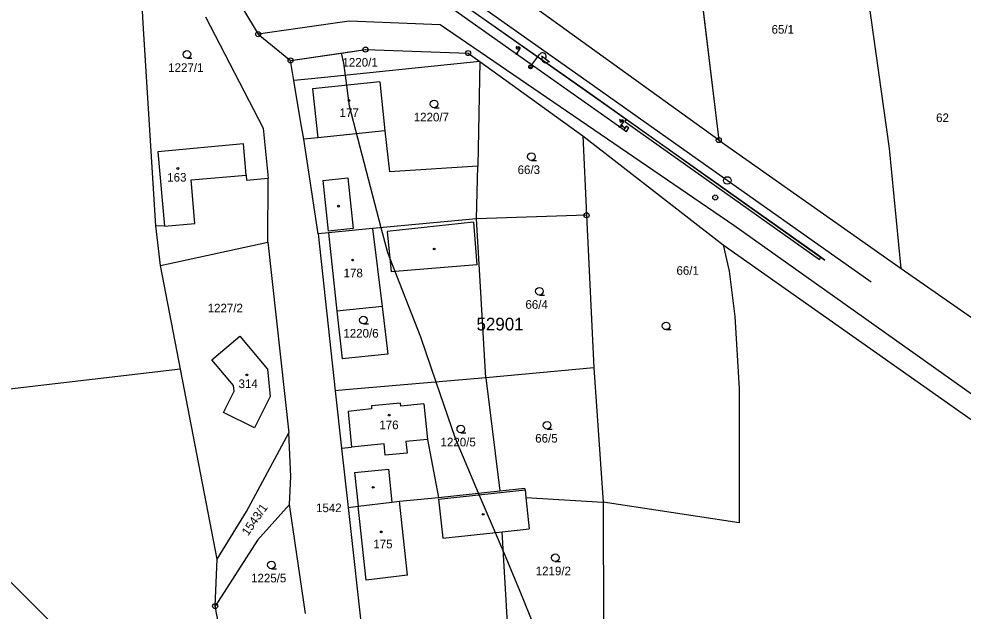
# Model space of a CAD drawing. Extents: x -777175 to -776673, y -1110537 to -1110036.
# Drawn here: x -776987.6 to -776801.4, y -1110431.1 to -1110314.3 of the extents above; entities that cross this region are included whole.
import ezdxf

# ---------------------------------------------------------------- set-up
doc = ezdxf.new("R2010")
doc.units = 0
for name, color, linetype in [('BPEJ', 7, 'Continuous'), ('GD_Demolice', 7, 'Continuous'), ('GD_Nový stav', 7, 'Continuous'), ('GD_Starý stav', 7, 'Continuous'), ('Katastr_HRANICE DRÁHY', 7, 'Continuous'), ('Katastr_Hranice parcel', 7, 'Continuous'), ('Katastr_Parcelní čísla', 7, 'Continuous'), ('Katastr_Slučkované čáry', 7, 'Continuous'), ('Katastr_Značky kultur', 7, 'Continuous'), ('Vrstva 7', 7, 'Continuous')]:
    doc.layers.add(name, color=color, linetype=linetype)

msp = doc.modelspace()

# ---------------------------------------------------------------- linework, layer by layer
at = {"layer": 'BPEJ'}
for points in [[(-776942.64, -1110471.49), (-776943.89, -1110463.76), (-776944.49, -1110457.52), (-776946.46, -1110445.63), (-776946.62, -1110444.42), (-776947.54, -1110437.37), (-776947.6, -1110436.89), (-776948.9, -1110430.12), (-776948.48, -1110420.89), (-776959.71, -1110362.93), (-776960.61, -1110355.15), (-776963.07, -1110315.22), (-776964.17, -1110295.07), (-776960.44, -1110293.63), (-776956.24, -1110294.15), (-776954.44, -1110298.36), (-776953.88, -1110294.2), (-776949.89, -1110285), (-776940.9, -1110291.45)], [(-776940.9, -1110291.45), (-776945.85, -1110300.04), (-776946.2, -1110307.65), (-776940.41, -1110317.34), (-776934.03, -1110322.5), (-776924.02, -1110321.07)], [(-776924.02, -1110321.07), (-776919.29, -1110320.39), (-776899.05, -1110321.06), (-776896.7, -1110322.75), (-776876.4, -1110337.37), (-776875.66, -1110353.06), (-776874.23, -1110383.12), (-776872.38, -1110409.66), (-776872.36, -1110434.4)], [(-776871.27, -1110465.42), (-776878.74, -1110452.04), (-776879.88, -1110449.23), (-776883.66, -1110439.87), (-776885.8, -1110434.57), (-776888.9, -1110426.9), (-776892.08, -1110419.38), (-776896.95, -1110407.86), (-776901.52, -1110397.06), (-776905.33, -1110385.94), (-776908.38, -1110377.06), (-776914.87, -1110360.44), (-776916.16, -1110355.5), (-776922.42, -1110331.54), (-776922.97, -1110327.43), (-776923.23, -1110325.46), (-776923.55, -1110323.06), (-776924.02, -1110321.07)]]:
    msp.add_lwpolyline(points, dxfattribs=at)
at = {"layer": 'Defpoints'}
msp.add_line((-776876.14, -1110537.25), (-777174.79, -1110241.95), dxfattribs=at)
at = {"layer": 'GD_Demolice'}
for p, q in [((-776886.5, -1110323.47), (-776884.98, -1110321.33)), ((-776884.55, -1110321.64), (-776882.96, -1110322.76)), ((-776887.07, -1110323.67), (-776886.42, -1110323.55)), ((-776887.05, -1110323.94), (-776886.34, -1110323.82))]:
    msp.add_line(p, q, dxfattribs=at)
msp.add_lwpolyline([(-776868.13, -1110334.57), (-776829.78, -1110361.74), (-776829.49, -1110361.33), (-776867.84, -1110334.16)], close=True, dxfattribs=at)
msp.add_circle((-776886.71, -1110323.78), 0.375, dxfattribs=at)
msp.add_circle((-776886.71, -1110323.78), 0.375, dxfattribs=at)
for centre, start, end in [((-776884.37, -1110321.76), 324.7342, 144.7342), ((-776883.76, -1110322.21), 144.0316, 325.4368)]:
    msp.add_arc(centre, 0.75, start, end, dxfattribs=at)
at = {"layer": 'GD_Nový stav'}
for p, q in [((-776909.86, -1110306.76), (-776889.46, -1110321.21)), ((-776888.97, -1110320.18), (-776889.57, -1110319.75)), ((-776889.38, -1110321.09), (-776888.81, -1110320.29)), ((-776889.48, -1110321.35), (-776889.52, -1110321.08)), ((-776889.46, -1110321.21), (-776868.26, -1110336.2)), ((-776889.38, -1110321.32), (-776889.42, -1110321.08)), ((-776868.58, -1110334.6), (-776869.18, -1110334.17)), ((-776868.99, -1110335.51), (-776868.42, -1110334.71)), ((-776868.59, -1110335.23), (-776868.81, -1110335.53)), ((-776868.13, -1110334.57), (-776867.84, -1110334.16)), ((-776869.09, -1110335.77), (-776869.13, -1110335.5)), ((-776868.98, -1110335.74), (-776869.02, -1110335.5)), ((-776868.7, -1110335.38), (-776868.09, -1110335.81)), ((-776868.09, -1110335.81), (-776868.34, -1110336.17)), ((-776868.34, -1110336.17), (-776867.83, -1110336.53)), ((-776867.84, -1110335.46), (-776868.09, -1110335.81)), ((-776867.33, -1110335.82), (-776867.84, -1110335.46)), ((-776867.83, -1110336.53), (-776867.33, -1110335.82))]:
    msp.add_line(p, q, dxfattribs=at)
for centre in [(-776889.46, -1110321.21), (-776889.46, -1110321.21), (-776869.07, -1110335.63), (-776869.07, -1110335.63)]:
    msp.add_circle(centre, 0.141, dxfattribs=at)
for centre, start, end in [((-776889.27, -1110319.97), 143.98, 325.3852), ((-776889.04, -1110320.13), 324.6826, 144.6826), ((-776868.88, -1110334.39), 143.98, 325.3852), ((-776868.65, -1110334.55), 324.6826, 144.6826)]:
    msp.add_arc(centre, 0.281, start, end, dxfattribs=at)
at = {"layer": 'GD_Starý stav'}
for points in [[(-776933.32, -1110287.93), (-776932.41, -1110288.39), (-776916.53, -1110299.75), (-776903.36, -1110309.07), (-776875.06, -1110329), (-776849.25, -1110347.3), (-776828.68, -1110361.9)], [(-776828.68, -1110361.9), (-776829.18, -1110361.55), (-776849.26, -1110347.33), (-776875, -1110329.07), (-776903.43, -1110309.03), (-776920.48, -1110296.98), (-776932.53, -1110288.41), (-776933.32, -1110287.93)], [(-776819.55, -1110366.24), (-776848.4, -1110345.85), (-776874.05, -1110327.7), (-776902.43, -1110307.63), (-776922.25, -1110293.6), (-776926.74, -1110290.42), (-776929.88, -1110288.2)]]:
    msp.add_lwpolyline(points, dxfattribs=at)
at = {"layer": 'Katastr_HRANICE DRÁHY'}
for points in [[(-776849.62, -1110338.22), (-776894.76, -1110305.65)], [(-776946.2, -1110307.65), (-776940.41, -1110317.34)], [(-776757.91, -1110417.68), (-776792.98, -1110393.16), (-776846.61, -1110355.09), (-776904.52, -1110315.47), (-776922.51, -1110314.75), (-776940.41, -1110317.34)], [(-776849.62, -1110338.22), (-776813.64, -1110363.55), (-776795.25, -1110376.34), (-776788.84, -1110380.33), (-776748.99, -1110408.66)]]:
    msp.add_lwpolyline(points, dxfattribs=at)
at = {"layer": 'Katastr_Hranice parcel'}
msp.add_line((-776854.31, -1110299.08), (-776849.62, -1110338.22), dxfattribs=at)
for points in [[(-776780.63, -1110277.66), (-776801.34, -1110279.1), (-776814.49, -1110280.25), (-776823.89, -1110281.93), (-776826.29, -1110267.5), (-776831.4, -1110267.85), (-776830.95, -1110273.53), (-776856.55, -1110275.29), (-776856.32, -1110281.19), (-776854.31, -1110299.08), (-776849.62, -1110338.22), (-776894.76, -1110305.65), (-776896.59, -1110304.32), (-776903.91, -1110299.01), (-776906.52, -1110296.78), (-776914.36, -1110290.06), (-776923.15, -1110282.87), (-776931.82, -1110275.9)], [(-776813.64, -1110363.55), (-776815.92, -1110339.86), (-776822.21, -1110295.34), (-776823.89, -1110281.93)], [(-776963.07, -1110315.22), (-776964.17, -1110295.07)], [(-776950.83, -1110313.89), (-776939.43, -1110335.86)], [(-776960.61, -1110355.15), (-776963.07, -1110315.22)], [(-776940.41, -1110317.34), (-776934.03, -1110322.5)], [(-776934.03, -1110322.5), (-776919.29, -1110320.39)], [(-776919.29, -1110320.39), (-776899.05, -1110321.06)], [(-776899.05, -1110321.06), (-776896.7, -1110322.75)], [(-776933.39, -1110326.49), (-776934.03, -1110322.5)], [(-776896.7, -1110322.75), (-776929.92, -1110326.14)], [(-776896.7, -1110322.75), (-776897.12, -1110343.35)], [(-776896.7, -1110322.75), (-776876.4, -1110337.37)], [(-776929.92, -1110326.14), (-776933.39, -1110326.49)], [(-776931.99, -1110334.85), (-776933.39, -1110326.49)], [(-776916.46, -1110326.75), (-776929.7, -1110328.14)], [(-776916.46, -1110326.75), (-776915.42, -1110336.37)], [(-776929.7, -1110328.14), (-776928.66, -1110337.76)], [(-776931.45, -1110338.05), (-776931.99, -1110334.85)], [(-776939.43, -1110335.86), (-776938.47, -1110345.76)], [(-776915.42, -1110336.37), (-776914.54, -1110344.5)], [(-776943.34, -1110338.96), (-776960.2, -1110340.54)], [(-776942.8, -1110345.12), (-776943.34, -1110338.96)], [(-776928.66, -1110337.76), (-776931.45, -1110338.05)], [(-776928.57, -1110356.7), (-776931.45, -1110338.05)], [(-776876.4, -1110337.37), (-776875.66, -1110353.06)], [(-776876.4, -1110337.37), (-776848.72, -1110358.87), (-776847.56, -1110364.06), (-776846.44, -1110372.99), (-776845.59, -1110387.18), (-776845.59, -1110413.73), (-776872.38, -1110409.66)], [(-776960.2, -1110340.54), (-776958.86, -1110355.2)], [(-776897.12, -1110343.35), (-776914.54, -1110344.5)], [(-776897.39, -1110353.76), (-776897.12, -1110343.35)], [(-776942.8, -1110345.12), (-776942.71, -1110346.13)], [(-776942.71, -1110346.13), (-776938.47, -1110345.76)], [(-776938.51, -1110358.35), (-776938.47, -1110345.76)], [(-776897.39, -1110353.76), (-776917.87, -1110355.66)], [(-776875.66, -1110353.06), (-776897.39, -1110353.76)], [(-776895.52, -1110385.09), (-776897.39, -1110353.76)], [(-776875.66, -1110353.06), (-776874.23, -1110383.12)], [(-776959.71, -1110362.93), (-776960.61, -1110355.15)], [(-776958.86, -1110355.2), (-776960.61, -1110355.15)], [(-776917.87, -1110355.66), (-776926.58, -1110356.51)], [(-776926.58, -1110356.51), (-776928.57, -1110356.7)], [(-776928.57, -1110356.7), (-776925.21, -1110387.65)], [(-776959.71, -1110362.93), (-776938.51, -1110358.35)], [(-776938.51, -1110358.35), (-776934.37, -1110395.94)], [(-776848.72, -1110358.87), (-776760.96, -1110420.76)], [(-776948.48, -1110420.89), (-776959.71, -1110362.93)], [(-776915.99, -1110371.01), (-776924.93, -1110371.95)], [(-776924.93, -1110371.95), (-776923.89, -1110381.39)], [(-776915.99, -1110371.01), (-776914.84, -1110380.44)], [(-776949.58, -1110381.53), (-776944.06, -1110376.89)], [(-776944.06, -1110376.89), (-776938.61, -1110383.37)], [(-776945.3, -1110386.64), (-776949.58, -1110381.53)], [(-776914.84, -1110380.44), (-776923.89, -1110381.39)], [(-777023.74, -1110391.3), (-776955.76, -1110383.34)], [(-776938.61, -1110383.37), (-776938.08, -1110388.81)], [(-776874.23, -1110383.12), (-776895.52, -1110385.09)], [(-776874.23, -1110383.12), (-776872.38, -1110409.66)], [(-776895.52, -1110385.09), (-776923.22, -1110387.48)], [(-776895.52, -1110385.09), (-776892.79, -1110407.42)], [(-776945.17, -1110387.71), (-776945.3, -1110386.64)], [(-776947.29, -1110391.94), (-776945.17, -1110387.71)], [(-776938.08, -1110388.81), (-776941.13, -1110394.94)], [(-776923.22, -1110387.48), (-776925.21, -1110387.65)], [(-776925.21, -1110387.65), (-776923.96, -1110398.98)], [(-776912.36, -1110390.08), (-776918.11, -1110390.66)], [(-776918.11, -1110390.66), (-776918.05, -1110391.25)], [(-776912.3, -1110390.67), (-776912.36, -1110390.08)], [(-776907.75, -1110390.21), (-776912.3, -1110390.67)], [(-776907.75, -1110390.21), (-776907.04, -1110397.24)], [(-776941.13, -1110394.94), (-776947.29, -1110391.94)], [(-776918.05, -1110391.25), (-776922.7, -1110391.72)], [(-776922.7, -1110391.72), (-776922.03, -1110398.78)], [(-776942.73, -1110411.46), (-776934.37, -1110395.94)], [(-776933.98, -1110404.58), (-776934.37, -1110395.94)], [(-776907.04, -1110397.24), (-776904.88, -1110408.71)], [(-776923.96, -1110398.98), (-776922.03, -1110398.78)], [(-776923.96, -1110398.98), (-776922.67, -1110410.67)], [(-776934.24, -1110410.08), (-776933.98, -1110404.58)], [(-776904.88, -1110408.71), (-776892.79, -1110407.42)], [(-776892.79, -1110407.42), (-776887.83, -1110406.89)], [(-776887.8, -1110407.19), (-776887.83, -1110406.89)], [(-776887.8, -1110407.19), (-776887.64, -1110408.68)], [(-776920.73, -1110410.44), (-776914.08, -1110409.64)], [(-776914.08, -1110409.64), (-776912.57, -1110409.46)], [(-776912.57, -1110409.46), (-776904.88, -1110408.71)], [(-776887.64, -1110408.68), (-776872.38, -1110409.66)], [(-776887.64, -1110408.68), (-776886.97, -1110414.92)], [(-776872.38, -1110409.66), (-776872.36, -1110434.4)], [(-776948.48, -1110420.89), (-776942.73, -1110411.46)], [(-776934.24, -1110410.08), (-776940.56, -1110417.1)], [(-776931.08, -1110431.61), (-776934.24, -1110410.08)], [(-776922.67, -1110410.67), (-776920.73, -1110410.44)], [(-776922.67, -1110410.67), (-776919.72, -1110437.38)], [(-776892.31, -1110415.49), (-776886.97, -1110414.92)], [(-776940.56, -1110417.1), (-776948.9, -1110430.12)], [(-776891.17, -1110434.64), (-776892.31, -1110415.49)], [(-776948.9, -1110430.12), (-776948.48, -1110420.89)], [(-776947.6, -1110436.89), (-776948.9, -1110430.12)]]:
    msp.add_lwpolyline(points, dxfattribs=at)
at = {"layer": 'Katastr_Slučkované čáry'}
for points in [[(-776915.42, -1110336.37), (-776928.66, -1110337.76)], [(-776953.66, -1110346.08), (-776942.8, -1110345.12)], [(-776952.88, -1110354.65), (-776953.66, -1110346.08)], [(-776927.7, -1110346.2), (-776922.76, -1110345.68)], [(-776927.7, -1110346.2), (-776926.64, -1110356.16)], [(-776922.76, -1110345.68), (-776921.68, -1110355.68)], [(-776958.86, -1110355.2), (-776952.88, -1110354.65)], [(-776921.68, -1110355.68), (-776926.64, -1110356.16)], [(-776917.87, -1110355.66), (-776915.99, -1110371.01)], [(-776897.95, -1110354.4), (-776914.98, -1110356.23)], [(-776897.95, -1110354.4), (-776897.3, -1110362.8)], [(-776926.58, -1110356.51), (-776924.93, -1110371.95)], [(-776914.98, -1110356.23), (-776914.17, -1110364.23)], [(-776897.3, -1110362.8), (-776914.17, -1110364.23)], [(-776915.6, -1110398.12), (-776922.03, -1110398.78)], [(-776915.36, -1110400.39), (-776915.6, -1110398.12)], [(-776907.04, -1110397.24), (-776911.29, -1110397.68)], [(-776911.29, -1110397.68), (-776911.06, -1110399.95)], [(-776911.06, -1110399.95), (-776915.36, -1110400.39)], [(-776921.41, -1110403.78), (-776914.74, -1110403.1)], [(-776921.41, -1110403.78), (-776920.73, -1110410.44)], [(-776914.74, -1110403.1), (-776914.08, -1110409.64)], [(-776904.85, -1110409.01), (-776887.8, -1110407.19)], [(-776910.98, -1110424.03), (-776912.57, -1110409.46)], [(-776904.85, -1110409.01), (-776904.02, -1110416.74)], [(-776919.14, -1110425.01), (-776920.73, -1110410.44)], [(-776904.02, -1110416.74), (-776892.31, -1110415.49)], [(-776910.98, -1110424.03), (-776919.14, -1110425.01)]]:
    msp.add_lwpolyline(points, dxfattribs=at)
at = {"layer": 'Katastr_Značky kultur'}
for p, q in [((-776940.46, -1110317.34), (-776940.36, -1110317.34)), ((-776954.48, -1110322.08), (-776953.48, -1110322.08)), ((-776919.34, -1110320.39), (-776919.24, -1110320.39)), ((-776899.1, -1110321.06), (-776899, -1110321.06)), ((-776934.08, -1110322.5), (-776933.98, -1110322.5)), ((-776905.75, -1110331.84), (-776904.75, -1110331.84)), ((-776849.67, -1110338.22), (-776849.57, -1110338.22)), ((-776886.56, -1110342.22), (-776885.56, -1110342.22)), ((-776875.71, -1110353.06), (-776875.61, -1110353.06)), ((-776884.98, -1110368.79), (-776883.98, -1110368.79)), ((-776919.67, -1110374.47), (-776918.67, -1110374.47)), ((-776860, -1110375.61), (-776859, -1110375.61)), ((-776900.47, -1110395.93), (-776899.47, -1110395.93)), ((-776883.47, -1110395.21), (-776882.47, -1110395.21)), ((-776937.82, -1110422.75), (-776936.82, -1110422.75)), ((-776881.84, -1110421.35), (-776880.84, -1110421.35)), ((-776948.95, -1110430.12), (-776948.85, -1110430.12))]:
    msp.add_line(p, q, dxfattribs=at)
for centre, radius in [((-776940.41, -1110317.34), 0.499), ((-776919.29, -1110320.39), 0.499), ((-776954.48, -1110321.33), 0.75), ((-776934.03, -1110322.5), 0.499), ((-776899.05, -1110321.06), 0.499), ((-776922.51, -1110330.42), 0.175), ((-776905.75, -1110331.09), 0.75), ((-776849.62, -1110338.22), 0.499), ((-776886.56, -1110341.47), 0.75), ((-776956.26, -1110343.82), 0.175), ((-776924.56, -1110351.26), 0.175), ((-776875.66, -1110353.06), 0.499), ((-776905.7, -1110359.7), 0.175), ((-776921.79, -1110361.89), 0.175), ((-776884.98, -1110368.04), 0.75), ((-776919.67, -1110373.72), 0.75), ((-776860, -1110374.86), 0.75), ((-776942.66, -1110384.53), 0.175), ((-776914.6, -1110392.46), 0.175), ((-776900.47, -1110395.18), 0.75), ((-776883.47, -1110394.46), 0.75), ((-776917.74, -1110406.7), 0.175), ((-776896.07, -1110412.03), 0.175), ((-776916.16, -1110415.5), 0.175), ((-776881.84, -1110420.6), 0.75), ((-776937.82, -1110422), 0.75), ((-776948.9, -1110430.12), 0.499)]:
    msp.add_circle(centre, radius, dxfattribs=at)
at = {"layer": 'Vrstva 7'}
msp.add_line((-776850.24, -1110349.57), (-776850.33, -1110349.51), dxfattribs=at)
for centre, radius in [((-776847.92, -1110346.19), 0.75), ((-776850.29, -1110349.54), 0.5)]:
    msp.add_circle(centre, radius, dxfattribs=at)

# ---------------------------------------------------------------- texts
at = {"layer": 'BPEJ'}
msp.add_text('52901', height=2.5, dxfattribs=at).set_placement((-776897.38, -1110375.76))
at = {"layer": 'Katastr_Parcelní čísla'}
for s, p in [('65/1', (-776839.2, -1110317.24)), ('1220/1', (-776923.8, -1110323.74)), ('1227/1', (-776958.16, -1110324.78)), ('177', (-776924.38, -1110333.69)), ('1220/7', (-776909.75, -1110334.54)), ('62', (-776806.76, -1110334.67)), ('66/3', (-776889.27, -1110344.92)), ('163', (-776958.35, -1110346.41)), ('66/1', (-776857.95, -1110364.79)), ('178', (-776923.58, -1110365.28)), ('1227/2', (-776950.38, -1110372.2)), ('66/4', (-776887.73, -1110371.49)), ('1220/6', (-776923.63, -1110377.17)), ('314', (-776944.29, -1110387.13)), ('176', (-776916.53, -1110395.24)), ('66/5', (-776885.8, -1110397.88)), ('1220/5', (-776904.47, -1110398.63)), ('1542', (-776929.02, -1110411.6)), ('175', (-776917.72, -1110418.73)), ('1219/2', (-776885.7, -1110424.05)), ('1225/5', (-776941.82, -1110425.45))]:
    msp.add_text(s, height=1.7, dxfattribs=at).set_placement(p)
msp.add_text('1543/1', height=1.7, rotation=55.0543, dxfattribs=at).set_placement((-776942.42, -1110416.39))

doc.saveas('drawing.dxf')
